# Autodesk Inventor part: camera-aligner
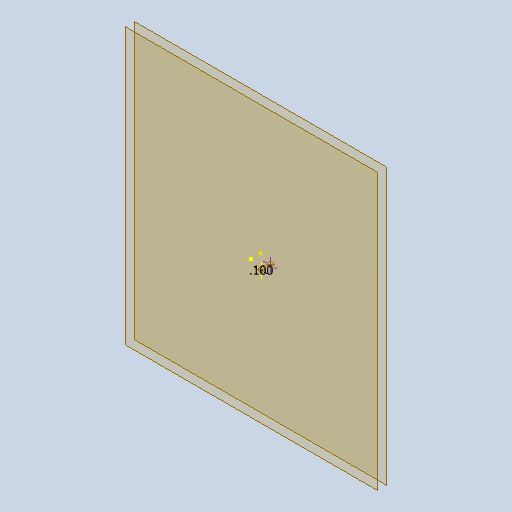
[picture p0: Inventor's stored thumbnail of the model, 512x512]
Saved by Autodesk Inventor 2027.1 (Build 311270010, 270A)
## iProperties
Created: 2026-08
Part Number: camera-aligner
Material: Generic
Document SubType Name: Modeling
Designer: dunge
Density: 1 g/cm^3
Appearance: Default
Author: dunge
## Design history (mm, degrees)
workplane "Work Plane1"
sketch "Sketch1"
  geometry: 2 further points
  dimensions: "d0" = 2.54 dimension on point (0, 0) point (1087.029, -585.81)
workplane "Work Plane2"
sketch "Sketch2"
  geometry: 3 further points
  constraints: 1 horizontal alignment
  dimensions: "d0" = 2.54 dimension on point (0, 0) point (1084.489, -585.81) point (1087.029, -585.81); "d0" = 2.54 distance of point (1084.489, -585.81) point (1087.029, -585.81)
node "view 1 target"
node "view 1 position"
